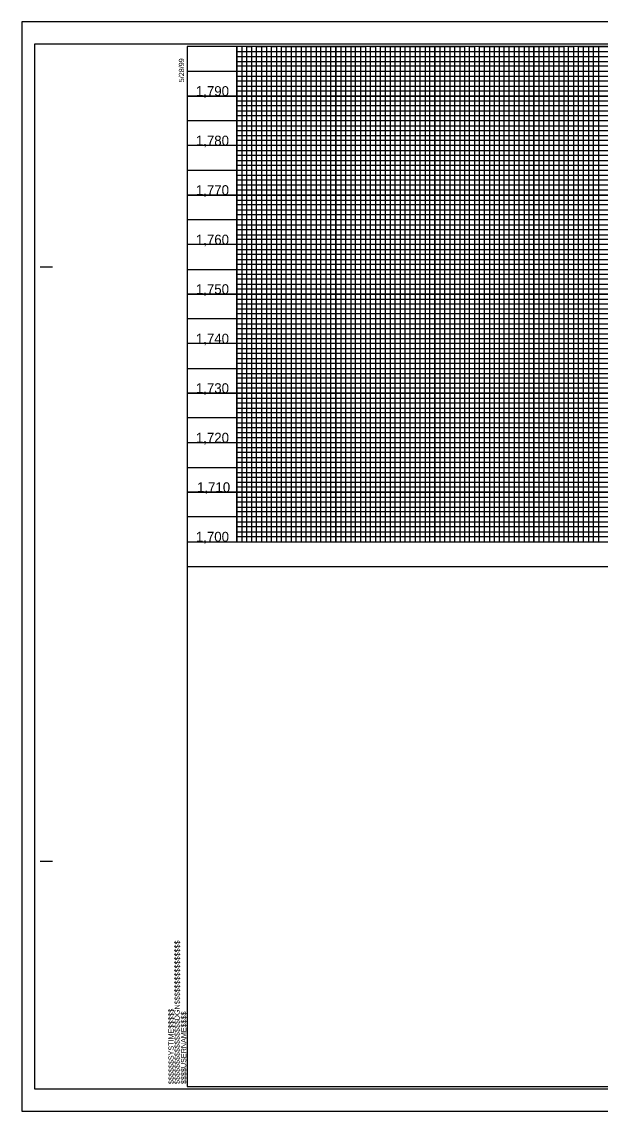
# Model space of a CAD drawing. Extents: x 505237 to 506921, y 424821 to 425921.
# Drawn here: x 505237 to 505821, y 424821 to 425921 of the extents above; entities that cross this region are included whole.
import ezdxf

# ---------------------------------------------------------------- set-up
doc = ezdxf.new("R2010")
doc.units = 0
for name, color, linetype in [('Exist Vertical Profile Vertical Axis Label', 7, 'Continuous'), ('Matchline', 7, 'Continuous'), ('Prop Horizontal Alignment Station Label', 7, 'Continuous'), ('Sheet Cutting Line CELL', 7, 'Continuous'), ('Sheet DOT Grid CELL', 7, 'Continuous'), ('Sheet Plot Border Inside CELL', 7, 'Continuous'), ('Sheet Plot Border Outside CELL', 7, 'Continuous'), ('Sheet Sticker Incomplete CELL', 7, 'Continuous')]:
    doc.layers.add(name, color=color, linetype=linetype)

msp = doc.modelspace()

# ---------------------------------------------------------------- linework, layer by layer
at = {"layer": 'Matchline'}
msp.add_line((505403.7, 425870.7), (506703.7, 425870.7), dxfattribs=at)
for points in [[(505478.7, 425895.7), (505478.7, 425395.7), (505528.7, 425395.7), (505528.7, 425895.7), (505578.7, 425895.7), (505578.7, 425395.7), (505628.7, 425395.7), (505628.7, 425895.7), (505678.7, 425895.7), (505678.7, 425395.7), (505728.7, 425395.7), (505728.7, 425895.7), (505778.7, 425895.7), (505778.7, 425395.7), (505828.7, 425395.7)], [(506703.7, 425820.7), (505403.7, 425820.7), (505403.7, 425770.7), (506703.7, 425770.7)], [(506903.7, 425720.7), (505403.7, 425720.7), (505403.7, 425670.7), (506728.7, 425670.7)], [(506903.7, 425620.7), (505403.7, 425620.7), (505403.7, 425570.7), (506903.7, 425570.7)], [(506903.7, 425520.7), (505403.7, 425520.7), (505403.7, 425470.7), (506903.7, 425470.7)], [(506903.7, 425420.7), (505403.7, 425420.7)]]:
    msp.add_lwpolyline(points, dxfattribs=at)
at = {"layer": 'Prop Horizontal Alignment Station Label'}
for p, q in [((505255.2, 425673.2), (505267.7, 425673.2)), ((505403.7, 425395.7), (506903.7, 425395.7)), ((505403.7, 425370.7), (506903.7, 425370.7)), ((505255.2, 425073.2), (505267.7, 425073.2)), ((505403.7, 424845.7), (506903.7, 424845.7)), ((505403.7, 424845.7), (505403.7, 424845.7)), ((505403.7, 424845.7), (505403.7, 424845.7)), ((505403.7, 424845.7), (505403.7, 424845.7)), ((505403.7, 424845.7), (505403.7, 424845.7)), ((505403.7, 424845.7), (505403.7, 424845.7)), ((505403.7, 424845.7), (505403.7, 424845.7)), ((505403.7, 424845.7), (505403.7, 424845.7))]:
    msp.add_line(p, q, dxfattribs=at)
msp.add_lwpolyline([(506903.7, 425895.7), (505403.7, 425895.7), (505403.7, 424845.7), (506903.7, 424845.7)], close=True, dxfattribs=at)
msp.add_lwpolyline([(505441.2, 424845.7), (505441.2, 424845.7)], dxfattribs=at)
at = {"layer": 'Sheet Cutting Line CELL'}
for p, q in [((506920.7, 425920.7), (505236.7, 425920.7)), ((505236.7, 425920.7), (505236.7, 424820.7)), ((505403.7, 424870.7), (505403.7, 424870.7)), ((505236.7, 424820.7), (506920.7, 424820.7))]:
    msp.add_line(p, q, dxfattribs=at)
for points in [[(505453.7, 425895.7), (505453.7, 425395.7), (505503.7, 425395.7), (505503.7, 425895.7), (505553.7, 425895.7), (505553.7, 425395.7), (505603.7, 425395.7), (505603.7, 425895.7), (505653.7, 425895.7), (505653.7, 425395.7), (505703.7, 425395.7), (505703.7, 425895.7), (505753.7, 425895.7), (505753.7, 425395.7), (505803.7, 425395.7), (505803.7, 425895.7), (505853.7, 425895.7)], [(505403.7, 425845.7), (506703.7, 425845.7)], [(506703.7, 425795.7), (505403.7, 425795.7), (505403.7, 425745.7), (506703.7, 425745.7)], [(506903.7, 425695.7), (505403.7, 425695.7), (505403.7, 425645.7), (506903.7, 425645.7)], [(506903.7, 425595.7), (505403.7, 425595.7), (505403.7, 425545.7), (506903.7, 425545.7)], [(506903.7, 425495.7), (505403.7, 425495.7), (505403.7, 425495.7), (505403.7, 425445.7), (506903.7, 425445.7)]]:
    msp.add_lwpolyline(points, dxfattribs=at)
at = {"layer": 'Sheet DOT Grid CELL'}
for p, q in [((505453.7, 425395.7), (505453.7, 425895.7)), ((505503.7, 425395.7), (505503.7, 425895.7)), ((505553.7, 425395.7), (505553.7, 425895.7)), ((505603.7, 425395.7), (505603.7, 425895.7)), ((505653.7, 425395.7), (505653.7, 425895.7)), ((505703.7, 425395.7), (505703.7, 425895.7)), ((505753.7, 425395.7), (505753.7, 425895.7)), ((505803.7, 425395.7), (505803.7, 425895.7)), ((506703.7, 425845.7), (505403.7, 425845.7)), ((506703.7, 425795.7), (505403.7, 425795.7)), ((506703.7, 425745.7), (505403.7, 425745.7)), ((506903.7, 425695.7), (505403.7, 425695.7)), ((506903.7, 425645.7), (505403.7, 425645.7)), ((506903.7, 425595.7), (505403.7, 425595.7)), ((506903.7, 425545.7), (505403.7, 425545.7)), ((506903.7, 425495.7), (505403.7, 425495.7)), ((506903.7, 425445.7), (505403.7, 425445.7)), ((505403.7, 425370.7), (506903.6, 425370.7))]:
    msp.add_line(p, q, dxfattribs=at)
at = {"layer": 'Sheet Plot Border Inside CELL'}
msp.add_lwpolyline([(505249.7, 424843.1), (506916.2, 424843.1), (506916.2, 425898.2), (505249.7, 425898.2)], close=True, dxfattribs=at)
at = {"layer": 'Sheet Plot Border Outside CELL'}
msp.add_lwpolyline([(505236.7, 424820.7), (506920.7, 424820.7), (506920.7, 425920.7), (505236.7, 425920.7)], close=True, dxfattribs=at)
at = {"layer": 'Sheet Sticker Incomplete CELL'}
for p, q in [((505453.7, 425890.7), (506703.7, 425890.7)), ((505453.7, 425885.7), (505453.7, 425885.7)), ((506703.7, 425885.7), (505453.7, 425885.3)), ((505453.7, 425880.7), (506703.7, 425880.7)), ((506703.7, 425760.7), (505453.7, 425760.7)), ((506703.7, 425755.7), (505453.7, 425755.7)), ((506703.7, 425750.7), (505453.7, 425750.7)), ((505453.7, 425740.7), (506703.7, 425740.7)), ((506703.7, 425735.7), (505453.7, 425735.7)), ((505453.7, 425730.7), (506853.7, 425730.7)), ((506853.7, 425710.7), (505453.7, 425710.7)), ((505453.7, 425705.7), (506853.7, 425705.7)), ((506853.7, 425685.7), (505453.7, 425685.7)), ((505453.7, 425680.7), (506853.7, 425680.7)), ((506853.7, 425660.7), (505453.7, 425660.7)), ((505453.7, 425655.7), (506853.7, 425655.7)), ((506853.7, 425650.7), (505453.7, 425650.7)), ((505453.7, 425640.7), (506853.7, 425640.7)), ((506853.7, 425635.7), (505453.7, 425635.7)), ((505453.7, 425630.7), (506853.7, 425630.7)), ((506853.7, 425625.7), (505453.7, 425625.7)), ((505453.7, 425615.7), (506853.7, 425615.7)), ((506853.7, 425610.7), (505453.7, 425610.7)), ((505453.7, 425605.7), (506853.7, 425605.7)), ((506853.7, 425600.7), (505453.7, 425600.7)), ((505453.7, 425590.7), (506853.7, 425590.7)), ((506853.7, 425585.7), (505453.7, 425585.7)), ((505453.7, 425580.7), (506853.7, 425580.7)), ((506853.7, 425575.7), (505453.7, 425575.7)), ((505453.7, 425565.7), (506853.7, 425565.7)), ((506853.7, 425560.7), (505453.7, 425560.7)), ((505453.7, 425555.7), (506853.7, 425555.7)), ((506853.7, 425550.7), (505453.7, 425550.7)), ((505453.7, 425540.7), (506853.7, 425540.7)), ((506853.7, 425535.7), (505453.7, 425535.7)), ((505453.7, 425530.7), (506853.7, 425530.7)), ((506853.7, 425525.7), (505453.7, 425525.7)), ((505453.7, 425515.7), (506853.7, 425515.7)), ((506853.7, 425510.7), (505453.7, 425510.7)), ((506853.7, 425505.7), (505453.7, 425505.7)), ((506853.7, 425500.7), (505453.7, 425500.7)), ((505453.7, 425490.7), (506853.7, 425490.7)), ((506853.7, 425485.7), (505453.7, 425485.7)), ((505453.7, 425480.7), (506853.7, 425480.7)), ((506853.7, 425475.7), (505453.7, 425475.7)), ((505453.7, 425465.7), (506853.7, 425465.7)), ((506853.7, 425460.7), (505453.7, 425460.7)), ((505453.7, 425455.7), (506853.7, 425455.7)), ((506853.7, 425450.7), (505453.7, 425450.7)), ((505453.7, 425440.7), (506853.7, 425440.7)), ((506853.7, 425435.7), (505453.7, 425435.7)), ((505453.7, 425430.7), (506853.7, 425430.7)), ((506853.7, 425425.7), (505453.7, 425425.7)), ((505453.7, 425415.7), (506853.7, 425415.7)), ((506853.7, 425410.7), (505453.7, 425410.7)), ((505453.7, 425405.7), (506853.7, 425405.7))]:
    msp.add_line(p, q, dxfattribs=at)
for points in [[(505458.7, 425895.7), (505458.7, 425395.7), (505463.7, 425395.7), (505463.7, 425895.7), (505468.7, 425895.7), (505468.7, 425395.7), (505473.7, 425395.7), (505473.7, 425895.7), (505483.7, 425895.7), (505483.7, 425395.7), (505488.7, 425395.7), (505488.7, 425895.7), (505493.7, 425895.7), (505493.7, 425395.7), (505498.7, 425395.7), (505508.7, 425395.7), (505513.7, 425395.7), (505513.7, 425895.7), (505518.7, 425895.7), (505518.7, 425395.7), (505523.7, 425395.7), (505523.7, 425895.7), (505533.7, 425895.7), (505533.7, 425395.7), (505538.7, 425395.7), (505538.7, 425895.7), (505543.7, 425895.7), (505543.7, 425395.7), (505548.7, 425395.7), (505548.7, 425895.7), (505558.7, 425895.7), (505558.7, 425395.7), (505563.7, 425395.7), (505563.7, 425895.7), (505568.7, 425895.7), (505568.7, 425395.7), (505573.7, 425395.7), (505573.7, 425895.7), (505583.7, 425895.7), (505583.7, 425395.7), (505588.7, 425395.7), (505588.7, 425895.7), (505593.7, 425895.7), (505593.7, 425395.7), (505598.7, 425395.7), (505598.7, 425895.7), (505608.7, 425895.7), (505608.7, 425395.7), (505613.7, 425395.7), (505613.7, 425895.7), (505618.7, 425895.7), (505618.7, 425395.7), (505623.7, 425395.7), (505623.7, 425895.7), (505633.7, 425895.7), (505633.7, 425395.7), (505638.7, 425395.7), (505638.7, 425895.7), (505643.7, 425895.7), (505643.7, 425395.7), (505648.7, 425395.7), (505648.7, 425895.7), (505658.7, 425895.7), (505658.7, 425395.7), (505663.7, 425395.7), (505663.7, 425895.7), (505668.7, 425895.7), (505668.7, 425395.7)], [(505498.7, 425395.7), (505498.7, 425895.7), (505508.7, 425895.7), (505508.7, 425395.7)], [(505668.7, 425395.7), (505673.7, 425395.7), (505673.7, 425895.7), (505683.7, 425895.7), (505683.7, 425395.7), (505688.7, 425395.7), (505688.7, 425895.7), (505693.7, 425895.7), (505693.7, 425395.7), (505698.7, 425395.7), (505698.7, 425895.7), (505708.7, 425895.7), (505708.7, 425395.7), (505713.7, 425395.7), (505713.7, 425895.7), (505718.7, 425895.7), (505718.7, 425395.7), (505723.7, 425395.7), (505723.7, 425895.7), (505733.7, 425895.7), (505733.7, 425395.7), (505738.7, 425395.7), (505738.7, 425895.7), (505743.7, 425895.7), (505743.7, 425395.7), (505748.7, 425395.7), (505748.7, 425895.7), (505758.7, 425895.7), (505758.7, 425395.7), (505763.7, 425395.7), (505763.7, 425895.7), (505768.7, 425895.7), (505768.7, 425395.7), (505773.7, 425395.7), (505773.7, 425895.7), (505783.7, 425895.7), (505783.7, 425395.7), (505788.7, 425395.7), (505788.7, 425895.7), (505793.7, 425895.7), (505793.7, 425395.7), (505798.7, 425395.7), (505798.7, 425895.7), (505808.7, 425895.7), (505808.7, 425395.7), (505813.7, 425395.7), (505813.7, 425895.7), (505818.7, 425895.7), (505818.7, 425395.7), (505823.7, 425395.7)], [(506703.7, 425875.7), (505453.7, 425875.7), (505453.7, 425865.7), (506703.7, 425865.7)], [(506703.7, 425860.7), (505453.7, 425860.7), (505453.7, 425855.7), (506703.7, 425855.7)], [(506703.7, 425850.7), (505453.7, 425850.7), (505453.7, 425840.7), (506703.7, 425840.7)], [(506703.7, 425835.7), (505453.7, 425835.7), (505453.7, 425830.7), (506703.7, 425830.7)], [(506703.7, 425825.7), (505453.7, 425825.7), (505453.7, 425815.7), (506703.7, 425815.7)], [(506703.7, 425810.7), (505453.7, 425810.7), (505453.7, 425805.7), (506703.7, 425805.7)], [(506703.7, 425800.7), (505453.7, 425800.7), (505453.7, 425790.7), (506703.7, 425790.7)], [(506703.7, 425785.6), (505453.8, 425785.6), (505453.8, 425780.7), (506703.7, 425780.7)], [(506703.7, 425775.7), (505453.7, 425775.7), (505453.7, 425765.7), (506703.7, 425765.7)], [(506853.7, 425725.7), (505453.7, 425725.7), (505453.7, 425715.7), (506853.7, 425715.7)], [(506853.7, 425700.7), (505453.7, 425700.7), (505453.7, 425690.7), (506853.7, 425690.7)], [(506853.7, 425675.7), (505453.7, 425675.7), (505453.7, 425665.7), (506853.7, 425665.7)], [(506853.7, 425400.7), (505453.7, 425400.7)]]:
    msp.add_lwpolyline(points, dxfattribs=at)

# ---------------------------------------------------------------- texts
at = {"layer": 'Exist Vertical Profile Vertical Axis Label'}
for s, p in [('1,790', (505412.4, 425845.7)), ('1,780', (505412.4, 425795.7)), ('1,770', (505412.4, 425745.7)), ('1,760', (505412.4, 425695.7)), ('1,750', (505412.4, 425645.7)), ('1,740', (505412.4, 425595.7)), ('1,730', (505412.4, 425545.7)), ('1,720', (505412.4, 425495.7)), ('1,710', (505413.6, 425445.7)), ('1,700', (505412.4, 425395.7))]:
    msp.add_text(s, height=10, dxfattribs=at).set_placement(p)
at = {"layer": 'Prop Horizontal Alignment Station Label'}
for s, p in [('5/28/99', (505400.5, 425859.6)), ('$$$$$$$$$$$$$$$$DGN$$$$$$$$$$$$$$$$', (505396.1, 424848)), ('$$$$$$SYSTIME$$$$$', (505390, 424848)), ('$$$$USERNAME$$$$', (505402.7, 424848.1))]:
    msp.add_text(s, height=5.25, rotation=90, dxfattribs=at).set_placement(p)

doc.saveas('drawing.dxf')
